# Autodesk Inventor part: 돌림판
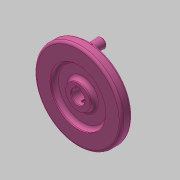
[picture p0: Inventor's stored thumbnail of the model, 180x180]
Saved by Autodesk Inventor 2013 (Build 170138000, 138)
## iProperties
Created: 2019-09
Part Number: 돌림판
Material: 알루미늄 6061
Document SubType Name: Modeling
Designer: mduedu
Density: 2.71 g/cm^3
Mass: 83.7217 g
Surface Area: 107.333 cm^2
Volume: 30.8936 cm^3
Author: mduedu
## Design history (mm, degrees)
sketch "스케치1"
  geometry: L1 (0, 0)-(9, 0); L2 (9, 0)-(9, 36); L3 (9, 36)-(0, 36); L4 (0, 23)-(4, 23); L5 (4, 23)-(4, 10); L6 (4, 10)-(0, 10); L7 (0, 36)-(0, 23); L8 (0, 10)-(0, 0)
  constraints: 16 end point, 4 parallel, 2 horizontal, 2 perpendicular, 1 collinear
  dimensions: "d0" = 72 diameter of L3 L1; "d2" = 9 distance of L2.end L3.end; "d3" = 4 distance between parallel lines of L7 L5; "d4" = 20 diameter of L6 L1; "d5" = 46 diameter of L4 L1
revolve "회전1" sketch "스케치1" stored, may be unused: angle "d6" = 90 deg
fillet "모깎기1" dims "d7" = 3
sketch "스케치2"
  geometry: C1 r 4 at (0, 29); 1 further point
  constraints: 1 centre point, 1 vertical alignment
  dimensions: "d8" = 8 diameter of C1; "d9" = 29 distance of C1.centre point (0, 0)
extrude "돌출1" join sketch "스케치2" distance "d10" = 11; taper "d11" = 0 deg
fillet "모깎기2" dims "d12" = 2
fillet "모깎기3" dims "d13" = 2
chamfer "모따기1" distance "d14" = 1; stored, may be unused: second distance "d15" = 2, angle "d16" = 45 deg
sketch "스케치3"
  geometry: L1 (-2, 5.123)-(2, 5.123); L2 (2, 5.123)-(2, 7.3); L3 (2, 7.3)-(-2, 7.3); L4 (-2, 7.3)-(-2, 5.123); A1 r 5.5 centre (0, 0) between (-2, 5.123) and (2, 5.123); 1 further point
  constraints: 8 end point, 2 parallel, 2 point on circle, 1 centre point, 1 coincident, 1 horizontal, 1 perpendicular
  dimensions: "d17" = 11 diameter of A1; "d18" = 4 distance of L2.end L3.end; "d19" = 12.8 dimension on A1 L3
extrude "돌출2" cut sketch "스케치3" stored distance "d20" = 11; taper "d21" = 0 deg
chamfer "모따기2" distance "d22" = 0.5; stored, may be unused: second distance "d23" = 2, angle "d24" = 45 deg
sketch "스케치4"
  geometry: A1 r 5.5 centre (0, 0) between (-2, 5.123) and (2, 5.123) reference; 2 further points
  constraints: 1 point on circle
hole "구멍1" sketch "스케치4" at (0, -5.5) diameter "d25" = 2.459; stored, may be unused: countersink angle "d29" = 90 deg, drill point angle "d31" = 118 deg; dims "d26" = 6, "d27" = 4, "d28" = 2, "d30" = 5
node "솔리드1"
